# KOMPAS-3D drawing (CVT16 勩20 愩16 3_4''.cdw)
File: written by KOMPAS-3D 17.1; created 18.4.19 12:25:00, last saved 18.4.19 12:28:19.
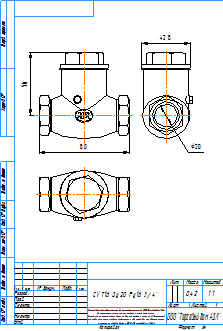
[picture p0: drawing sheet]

Sheet 1: A4, portrait

Title block, sheet 1: name: CVT16 Ду20 Ру16 3/4''; material: Внимание! Данный продукт является объектом авторского права ООО «Торговый Дом АДЛ». / Запрещается изменение, копирование, распространение / (в том числе путем копирования на другие сайты и ресурсы в Интернете) / или любое иное использование информации и объектов без предварительного / согласия правообладателя (ООО «Торговый Дом АДЛ»).; mass: 0,42; sheets: 1; organisation: ООО "Торговый дом АДЛ"; sheet format: A4; stored path: \\adlc.lan\data\АДЛ_ПКД\3D-модели\ADL production\Клапаны обратные ГРАНЛОК\CVT16\KOMPAS 2D\CVT16 Ду20 Ру16 3_4''.cdw

Views: Вид 1, Проекционный вид 2, Проекционный вид 3
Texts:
  user
Dimensions and other numbers on the sheet: 80; 56; 20; 42,8; 1:1; 1; 0,42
